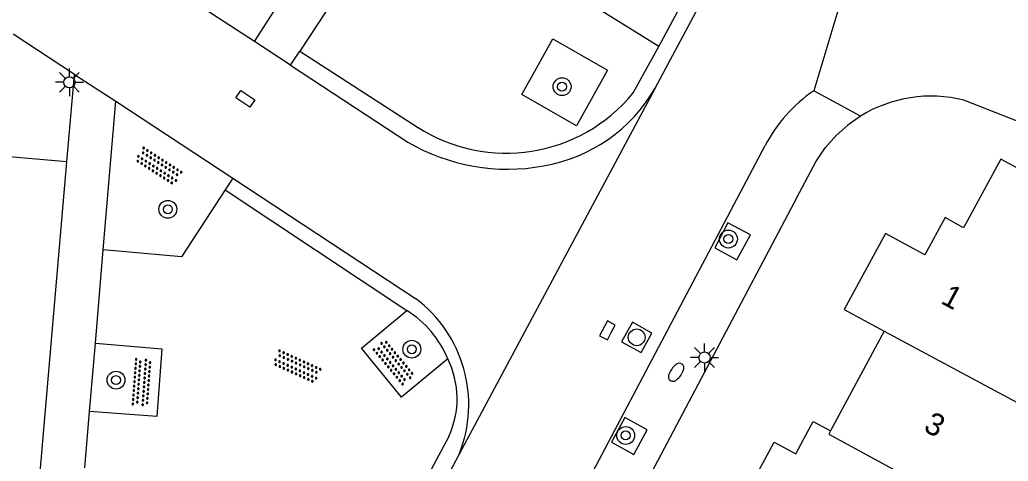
# Model space of a CAD drawing. Extents: x 136000 to 141000, y 400494 to 402006.
# Drawn here: x 137797.28 to 137841.52, y 401678.33 to 401698.08 of the extents above; entities that cross this region are included whole.
import ezdxf

# ---------------------------------------------------------------- set-up
doc = ezdxf.new("R2010")
doc.units = 0
for name, color, linetype in [('gg-afsc-hekwerk', 7, 'Continuous'), ('gg-afsc-muur', 7, 'Continuous'), ('gg-anno-huisnummerreeks BGT', 7, 'Continuous'), ('gg-bbg-hoofdgebouw', 7, 'Continuous'), ('gg-bbg-tussenscheiding', 7, 'Continuous'), ('gg-knt-verharding', 7, 'Continuous'), ('gg-knt-verharding nz', 7, 'Continuous'), ('gt-grn-groengrens', 7, 'Continuous'), ('gt-grn-weggrens', 7, 'Continuous'), ('gt-symb-boom', 7, 'Continuous'), ('gt-symb-brandkraan', 7, 'Continuous'), ('gt-symb-kolk', 7, 'Continuous'), ('gt-symb-kolk center center', 7, 'Continuous'), ('gt-symb-lichtmast', 7, 'Continuous'), ('gt-symb-overige verharding', 7, 'Continuous'), ('gt-symb-rioolschacht', 7, 'Continuous')]:
    doc.layers.add(name, color=color, linetype=linetype)

# ---------------------------------------------------------------- blocks, each defined once
blk = doc.blocks.new('gt0-LMAST')
at = {"layer": 'gt-symb-lichtmast'}
for p, q in [((-0.005, 0.246), (-0.005, 0.621)), ((-0.182, 0.173), (-0.447, 0.438)), ((0.172, 0.173), (0.437, 0.438)), ((-0.255, -0.004), (-0.63, -0.004)), ((-0.182, -0.181), (-0.447, -0.446)), ((-0.005, -0.254), (-0.005, -0.629)), ((0.437, -0.446), (0.172, -0.181)), ((0.245, -0.004), (0.62, -0.004))]:
    blk.add_line(p, q, dxfattribs=at)
blk.add_circle((-0.005, -0.004), 0.25, dxfattribs=at)
blk = doc.blocks.new('gt0-BOOM')
at = {"layer": 'gt-symb-boom'}
for radius in [0.4, 0.2]:
    blk.add_circle((0, 0), radius, dxfattribs=at)
blk = doc.blocks.new('gt0-RS')
at = {"layer": 'gt-symb-rioolschacht'}
blk.add_lwpolyline([(-0.5, -0.5), (0.5, -0.5), (0.5, 0.5), (-0.5, 0.5)], close=True, dxfattribs=at)
blk.add_circle((0, 0), 0.375, dxfattribs=at)
blk = doc.blocks.new('gt0-KOLK')
at = {"layer": 'gt-symb-kolk'}
blk.add_lwpolyline([(0, 0), (0.375, 0), (0.375, 0.4), (-0.375, 0.4), (-0.375, 0), (0, 0)], dxfattribs=at)
blk = doc.blocks.new('gt0-OVH')
at = {"layer": 'gt-symb-overige verharding'}
for points in [[(-0.972, 0.298), (-0.967, 0.308), (-0.965, 0.319), (-0.966, 0.33), (-0.971, 0.34), (-0.978, 0.348), (-0.988, 0.353), (-0.999, 0.355), (-1.01, 0.354), (-1.02, 0.349), (-1.028, 0.342), (-1.033, 0.332), (-1.035, 0.321), (-1.034, 0.31), (-1.029, 0.3), (-1.022, 0.292), (-1.012, 0.287), (-1.001, 0.285), (-0.99, 0.286), (-0.98, 0.291)], [(-0.872, 0.106), (-0.867, 0.116), (-0.865, 0.126), (-0.866, 0.137), (-0.871, 0.147), (-0.878, 0.156), (-0.888, 0.161), (-0.899, 0.163), (-0.91, 0.162), (-0.92, 0.157), (-0.928, 0.15), (-0.933, 0.14), (-0.935, 0.129), (-0.934, 0.118), (-0.929, 0.108), (-0.922, 0.1), (-0.912, 0.095), (-0.901, 0.092), (-0.89, 0.094), (-0.88, 0.098)], [(-0.772, 0.298), (-0.767, 0.308), (-0.765, 0.319), (-0.766, 0.33), (-0.771, 0.34), (-0.778, 0.348), (-0.788, 0.353), (-0.799, 0.355), (-0.81, 0.354), (-0.82, 0.349), (-0.828, 0.342), (-0.833, 0.332), (-0.835, 0.321), (-0.834, 0.31), (-0.829, 0.3), (-0.822, 0.292), (-0.812, 0.287), (-0.801, 0.285), (-0.79, 0.286), (-0.78, 0.291)], [(-0.672, 0.106), (-0.667, 0.116), (-0.665, 0.126), (-0.666, 0.137), (-0.671, 0.147), (-0.678, 0.156), (-0.688, 0.161), (-0.699, 0.163), (-0.71, 0.162), (-0.72, 0.157), (-0.728, 0.15), (-0.733, 0.14), (-0.735, 0.129), (-0.734, 0.118), (-0.729, 0.108), (-0.722, 0.1), (-0.712, 0.095), (-0.701, 0.092), (-0.69, 0.094), (-0.68, 0.098)], [(-0.572, 0.298), (-0.567, 0.308), (-0.565, 0.319), (-0.566, 0.33), (-0.571, 0.34), (-0.578, 0.348), (-0.588, 0.353), (-0.599, 0.355), (-0.61, 0.354), (-0.62, 0.349), (-0.628, 0.342), (-0.633, 0.332), (-0.635, 0.321), (-0.634, 0.31), (-0.629, 0.3), (-0.622, 0.292), (-0.612, 0.287), (-0.601, 0.285), (-0.59, 0.286), (-0.58, 0.291)], [(-0.472, 0.106), (-0.467, 0.116), (-0.465, 0.126), (-0.466, 0.137), (-0.471, 0.147), (-0.478, 0.156), (-0.488, 0.161), (-0.499, 0.163), (-0.51, 0.162), (-0.52, 0.157), (-0.528, 0.15), (-0.533, 0.14), (-0.535, 0.129), (-0.534, 0.118), (-0.529, 0.108), (-0.522, 0.1), (-0.512, 0.095), (-0.501, 0.092), (-0.49, 0.094), (-0.48, 0.098)], [(-0.372, 0.298), (-0.367, 0.308), (-0.365, 0.319), (-0.366, 0.33), (-0.371, 0.34), (-0.378, 0.348), (-0.388, 0.353), (-0.399, 0.355), (-0.41, 0.354), (-0.42, 0.349), (-0.428, 0.342), (-0.433, 0.332), (-0.435, 0.321), (-0.434, 0.31), (-0.429, 0.3), (-0.422, 0.292), (-0.412, 0.287), (-0.401, 0.285), (-0.39, 0.286), (-0.38, 0.291)], [(-0.272, 0.106), (-0.267, 0.116), (-0.265, 0.126), (-0.266, 0.137), (-0.271, 0.147), (-0.278, 0.156), (-0.288, 0.161), (-0.299, 0.163), (-0.31, 0.162), (-0.32, 0.157), (-0.328, 0.15), (-0.333, 0.14), (-0.335, 0.129), (-0.334, 0.118), (-0.329, 0.108), (-0.322, 0.1), (-0.312, 0.095), (-0.301, 0.092), (-0.29, 0.094), (-0.28, 0.098)], [(-0.172, 0.298), (-0.167, 0.308), (-0.165, 0.319), (-0.166, 0.33), (-0.171, 0.34), (-0.178, 0.348), (-0.188, 0.353), (-0.199, 0.355), (-0.21, 0.354), (-0.22, 0.349), (-0.228, 0.342), (-0.233, 0.332), (-0.235, 0.321), (-0.234, 0.31), (-0.229, 0.3), (-0.222, 0.292), (-0.212, 0.287), (-0.201, 0.285), (-0.19, 0.286), (-0.18, 0.291)], [(-0.072, 0.106), (-0.067, 0.116), (-0.065, 0.126), (-0.066, 0.137), (-0.071, 0.147), (-0.078, 0.156), (-0.088, 0.161), (-0.099, 0.163), (-0.11, 0.162), (-0.12, 0.157), (-0.128, 0.15), (-0.133, 0.14), (-0.135, 0.129), (-0.134, 0.118), (-0.129, 0.108), (-0.122, 0.1), (-0.112, 0.095), (-0.101, 0.092), (-0.09, 0.094), (-0.08, 0.098)], [(0.028, 0.298), (0.033, 0.308), (0.035, 0.319), (0.034, 0.33), (0.029, 0.34), (0.022, 0.348), (0.012, 0.353), (0.001, 0.355), (-0.01, 0.354), (-0.02, 0.349), (-0.028, 0.342), (-0.033, 0.332), (-0.035, 0.321), (-0.034, 0.31), (-0.029, 0.3), (-0.022, 0.292), (-0.012, 0.287), (-0.001, 0.285), (0.01, 0.286), (0.02, 0.291)], [(0.128, 0.106), (0.133, 0.116), (0.135, 0.126), (0.134, 0.137), (0.129, 0.147), (0.122, 0.156), (0.112, 0.161), (0.101, 0.163), (0.09, 0.162), (0.08, 0.157), (0.072, 0.15), (0.067, 0.14), (0.065, 0.129), (0.066, 0.118), (0.071, 0.108), (0.078, 0.1), (0.088, 0.095), (0.099, 0.092), (0.11, 0.094), (0.12, 0.098)], [(0.228, 0.298), (0.233, 0.308), (0.235, 0.319), (0.234, 0.33), (0.229, 0.34), (0.222, 0.348), (0.212, 0.353), (0.201, 0.355), (0.19, 0.354), (0.18, 0.349), (0.172, 0.342), (0.167, 0.332), (0.165, 0.321), (0.166, 0.31), (0.171, 0.3), (0.178, 0.292), (0.188, 0.287), (0.199, 0.285), (0.21, 0.286), (0.22, 0.291)], [(0.328, 0.106), (0.333, 0.116), (0.335, 0.126), (0.334, 0.137), (0.329, 0.147), (0.322, 0.156), (0.312, 0.161), (0.301, 0.163), (0.29, 0.162), (0.28, 0.157), (0.272, 0.15), (0.267, 0.14), (0.265, 0.129), (0.266, 0.118), (0.271, 0.108), (0.278, 0.1), (0.288, 0.095), (0.299, 0.092), (0.31, 0.094), (0.32, 0.098)], [(0.428, 0.298), (0.433, 0.308), (0.435, 0.319), (0.434, 0.33), (0.429, 0.34), (0.422, 0.348), (0.412, 0.353), (0.401, 0.355), (0.39, 0.354), (0.38, 0.349), (0.372, 0.342), (0.367, 0.332), (0.365, 0.321), (0.366, 0.31), (0.371, 0.3), (0.378, 0.292), (0.388, 0.287), (0.399, 0.285), (0.41, 0.286), (0.42, 0.291)], [(0.528, 0.106), (0.533, 0.116), (0.535, 0.126), (0.534, 0.137), (0.529, 0.147), (0.522, 0.156), (0.512, 0.161), (0.501, 0.163), (0.49, 0.162), (0.48, 0.157), (0.472, 0.15), (0.467, 0.14), (0.465, 0.129), (0.466, 0.118), (0.471, 0.108), (0.478, 0.1), (0.488, 0.095), (0.499, 0.092), (0.51, 0.094), (0.52, 0.098)], [(0.628, 0.298), (0.633, 0.308), (0.635, 0.319), (0.634, 0.33), (0.629, 0.34), (0.622, 0.348), (0.612, 0.353), (0.601, 0.355), (0.59, 0.354), (0.58, 0.349), (0.572, 0.342), (0.567, 0.332), (0.565, 0.321), (0.566, 0.31), (0.571, 0.3), (0.578, 0.292), (0.588, 0.287), (0.599, 0.285), (0.61, 0.286), (0.62, 0.291)], [(0.728, 0.106), (0.733, 0.116), (0.735, 0.126), (0.734, 0.137), (0.729, 0.147), (0.722, 0.156), (0.712, 0.161), (0.701, 0.163), (0.69, 0.162), (0.68, 0.157), (0.672, 0.15), (0.667, 0.14), (0.665, 0.129), (0.666, 0.118), (0.671, 0.108), (0.678, 0.1), (0.688, 0.095), (0.699, 0.092), (0.71, 0.094), (0.72, 0.098)], [(0.828, 0.298), (0.833, 0.308), (0.835, 0.319), (0.834, 0.33), (0.829, 0.34), (0.822, 0.348), (0.812, 0.353), (0.801, 0.355), (0.79, 0.354), (0.78, 0.349), (0.772, 0.342), (0.767, 0.332), (0.765, 0.321), (0.766, 0.31), (0.771, 0.3), (0.778, 0.292), (0.788, 0.287), (0.799, 0.285), (0.81, 0.286), (0.82, 0.291)], [(0.928, 0.106), (0.933, 0.116), (0.935, 0.126), (0.934, 0.137), (0.929, 0.147), (0.922, 0.156), (0.912, 0.161), (0.901, 0.163), (0.89, 0.162), (0.88, 0.157), (0.872, 0.15), (0.867, 0.14), (0.865, 0.129), (0.866, 0.118), (0.871, 0.108), (0.878, 0.1), (0.888, 0.095), (0.899, 0.092), (0.91, 0.094), (0.92, 0.098)], [(1.028, 0.298), (1.033, 0.308), (1.035, 0.319), (1.034, 0.33), (1.029, 0.34), (1.022, 0.348), (1.012, 0.353), (1.001, 0.355), (0.99, 0.354), (0.98, 0.349), (0.972, 0.342), (0.967, 0.332), (0.965, 0.321), (0.966, 0.31), (0.971, 0.3), (0.978, 0.292), (0.988, 0.287), (0.999, 0.285), (1.01, 0.286), (1.02, 0.291)], [(-0.972, -0.142), (-0.967, -0.132), (-0.965, -0.121), (-0.966, -0.11), (-0.971, -0.1), (-0.978, -0.092), (-0.988, -0.087), (-0.999, -0.085), (-1.01, -0.086), (-1.02, -0.091), (-1.028, -0.098), (-1.033, -0.108), (-1.035, -0.119), (-1.034, -0.13), (-1.029, -0.14), (-1.022, -0.148), (-1.012, -0.153), (-1.001, -0.155), (-0.99, -0.154), (-0.98, -0.149)], [(-0.872, -0.334), (-0.867, -0.324), (-0.865, -0.314), (-0.866, -0.303), (-0.871, -0.293), (-0.878, -0.284), (-0.888, -0.279), (-0.899, -0.277), (-0.91, -0.278), (-0.92, -0.283), (-0.928, -0.29), (-0.933, -0.3), (-0.935, -0.311), (-0.934, -0.322), (-0.929, -0.332), (-0.922, -0.34), (-0.912, -0.345), (-0.901, -0.348), (-0.89, -0.346), (-0.88, -0.342)], [(-0.772, -0.142), (-0.767, -0.132), (-0.765, -0.121), (-0.766, -0.11), (-0.771, -0.1), (-0.778, -0.092), (-0.788, -0.087), (-0.799, -0.085), (-0.81, -0.086), (-0.82, -0.091), (-0.828, -0.098), (-0.833, -0.108), (-0.835, -0.119), (-0.834, -0.13), (-0.829, -0.14), (-0.822, -0.148), (-0.812, -0.153), (-0.801, -0.155), (-0.79, -0.154), (-0.78, -0.149)], [(-0.672, -0.334), (-0.667, -0.324), (-0.665, -0.314), (-0.666, -0.303), (-0.671, -0.293), (-0.678, -0.284), (-0.688, -0.279), (-0.699, -0.277), (-0.71, -0.278), (-0.72, -0.283), (-0.728, -0.29), (-0.733, -0.3), (-0.735, -0.311), (-0.734, -0.322), (-0.729, -0.332), (-0.722, -0.34), (-0.712, -0.345), (-0.701, -0.348), (-0.69, -0.346), (-0.68, -0.342)], [(-0.572, -0.142), (-0.567, -0.132), (-0.565, -0.121), (-0.566, -0.11), (-0.571, -0.1), (-0.578, -0.092), (-0.588, -0.087), (-0.599, -0.085), (-0.61, -0.086), (-0.62, -0.091), (-0.628, -0.098), (-0.633, -0.108), (-0.635, -0.119), (-0.634, -0.13), (-0.629, -0.14), (-0.622, -0.148), (-0.612, -0.153), (-0.601, -0.155), (-0.59, -0.154), (-0.58, -0.149)], [(-0.472, -0.334), (-0.467, -0.324), (-0.465, -0.314), (-0.466, -0.303), (-0.471, -0.293), (-0.478, -0.284), (-0.488, -0.279), (-0.499, -0.277), (-0.51, -0.278), (-0.52, -0.283), (-0.528, -0.29), (-0.533, -0.3), (-0.535, -0.311), (-0.534, -0.322), (-0.529, -0.332), (-0.522, -0.34), (-0.512, -0.345), (-0.501, -0.348), (-0.49, -0.346), (-0.48, -0.342)], [(-0.372, -0.142), (-0.367, -0.132), (-0.365, -0.121), (-0.366, -0.11), (-0.371, -0.1), (-0.378, -0.092), (-0.388, -0.087), (-0.399, -0.085), (-0.41, -0.086), (-0.42, -0.091), (-0.428, -0.098), (-0.433, -0.108), (-0.435, -0.119), (-0.434, -0.13), (-0.429, -0.14), (-0.422, -0.148), (-0.412, -0.153), (-0.401, -0.155), (-0.39, -0.154), (-0.38, -0.149)], [(-0.272, -0.334), (-0.267, -0.324), (-0.265, -0.314), (-0.266, -0.303), (-0.271, -0.293), (-0.278, -0.284), (-0.288, -0.279), (-0.299, -0.277), (-0.31, -0.278), (-0.32, -0.283), (-0.328, -0.29), (-0.333, -0.3), (-0.335, -0.311), (-0.334, -0.322), (-0.329, -0.332), (-0.322, -0.34), (-0.312, -0.345), (-0.301, -0.348), (-0.29, -0.346), (-0.28, -0.342)], [(-0.172, -0.142), (-0.167, -0.132), (-0.165, -0.121), (-0.166, -0.11), (-0.171, -0.1), (-0.178, -0.092), (-0.188, -0.087), (-0.199, -0.085), (-0.21, -0.086), (-0.22, -0.091), (-0.228, -0.098), (-0.233, -0.108), (-0.235, -0.119), (-0.234, -0.13), (-0.229, -0.14), (-0.222, -0.148), (-0.212, -0.153), (-0.201, -0.155), (-0.19, -0.154), (-0.18, -0.149)], [(-0.072, -0.334), (-0.067, -0.324), (-0.065, -0.314), (-0.066, -0.303), (-0.071, -0.293), (-0.078, -0.284), (-0.088, -0.279), (-0.099, -0.277), (-0.11, -0.278), (-0.12, -0.283), (-0.128, -0.29), (-0.133, -0.3), (-0.135, -0.311), (-0.134, -0.322), (-0.129, -0.332), (-0.122, -0.34), (-0.112, -0.345), (-0.101, -0.348), (-0.09, -0.346), (-0.08, -0.342)], [(0.028, -0.142), (0.033, -0.132), (0.035, -0.121), (0.034, -0.11), (0.029, -0.1), (0.022, -0.092), (0.012, -0.087), (0.001, -0.085), (-0.01, -0.086), (-0.02, -0.091), (-0.028, -0.098), (-0.033, -0.108), (-0.035, -0.119), (-0.034, -0.13), (-0.029, -0.14), (-0.022, -0.148), (-0.012, -0.153), (-0.001, -0.155), (0.01, -0.154), (0.02, -0.149)], [(0.128, -0.334), (0.133, -0.324), (0.135, -0.314), (0.134, -0.303), (0.129, -0.293), (0.122, -0.284), (0.112, -0.279), (0.101, -0.277), (0.09, -0.278), (0.08, -0.283), (0.072, -0.29), (0.067, -0.3), (0.065, -0.311), (0.066, -0.322), (0.071, -0.332), (0.078, -0.34), (0.088, -0.345), (0.099, -0.348), (0.11, -0.346), (0.12, -0.342)], [(0.228, -0.142), (0.233, -0.132), (0.235, -0.121), (0.234, -0.11), (0.229, -0.1), (0.222, -0.092), (0.212, -0.087), (0.201, -0.085), (0.19, -0.086), (0.18, -0.091), (0.172, -0.098), (0.167, -0.108), (0.165, -0.119), (0.166, -0.13), (0.171, -0.14), (0.178, -0.148), (0.188, -0.153), (0.199, -0.155), (0.21, -0.154), (0.22, -0.149)], [(0.328, -0.334), (0.333, -0.324), (0.335, -0.314), (0.334, -0.303), (0.329, -0.293), (0.322, -0.284), (0.312, -0.279), (0.301, -0.277), (0.29, -0.278), (0.28, -0.283), (0.272, -0.29), (0.267, -0.3), (0.265, -0.311), (0.266, -0.322), (0.271, -0.332), (0.278, -0.34), (0.288, -0.345), (0.299, -0.348), (0.31, -0.346), (0.32, -0.342)], [(0.428, -0.142), (0.433, -0.132), (0.435, -0.121), (0.434, -0.11), (0.429, -0.1), (0.422, -0.092), (0.412, -0.087), (0.401, -0.085), (0.39, -0.086), (0.38, -0.091), (0.372, -0.098), (0.367, -0.108), (0.365, -0.119), (0.366, -0.13), (0.371, -0.14), (0.378, -0.148), (0.388, -0.153), (0.399, -0.155), (0.41, -0.154), (0.42, -0.149)], [(0.528, -0.334), (0.533, -0.324), (0.535, -0.314), (0.534, -0.303), (0.529, -0.293), (0.522, -0.284), (0.512, -0.279), (0.501, -0.277), (0.49, -0.278), (0.48, -0.283), (0.472, -0.29), (0.467, -0.3), (0.465, -0.311), (0.466, -0.322), (0.471, -0.332), (0.478, -0.34), (0.488, -0.345), (0.499, -0.348), (0.51, -0.346), (0.52, -0.342)], [(0.628, -0.142), (0.633, -0.132), (0.635, -0.121), (0.634, -0.11), (0.629, -0.1), (0.622, -0.092), (0.612, -0.087), (0.601, -0.085), (0.59, -0.086), (0.58, -0.091), (0.572, -0.098), (0.567, -0.108), (0.565, -0.119), (0.566, -0.13), (0.571, -0.14), (0.578, -0.148), (0.588, -0.153), (0.599, -0.155), (0.61, -0.154), (0.62, -0.149)], [(0.728, -0.334), (0.733, -0.324), (0.735, -0.314), (0.734, -0.303), (0.729, -0.293), (0.722, -0.284), (0.712, -0.279), (0.701, -0.277), (0.69, -0.278), (0.68, -0.283), (0.672, -0.29), (0.667, -0.3), (0.665, -0.311), (0.666, -0.322), (0.671, -0.332), (0.678, -0.34), (0.688, -0.345), (0.699, -0.348), (0.71, -0.346), (0.72, -0.342)], [(0.828, -0.142), (0.833, -0.132), (0.835, -0.121), (0.834, -0.11), (0.829, -0.1), (0.822, -0.092), (0.812, -0.087), (0.801, -0.085), (0.79, -0.086), (0.78, -0.091), (0.772, -0.098), (0.767, -0.108), (0.765, -0.119), (0.766, -0.13), (0.771, -0.14), (0.778, -0.148), (0.788, -0.153), (0.799, -0.155), (0.81, -0.154), (0.82, -0.149)], [(0.928, -0.334), (0.933, -0.324), (0.935, -0.314), (0.934, -0.303), (0.929, -0.293), (0.922, -0.284), (0.912, -0.279), (0.901, -0.277), (0.89, -0.278), (0.88, -0.283), (0.872, -0.29), (0.867, -0.3), (0.865, -0.311), (0.866, -0.322), (0.871, -0.332), (0.878, -0.34), (0.888, -0.345), (0.899, -0.348), (0.91, -0.346), (0.92, -0.342)], [(1.028, -0.142), (1.033, -0.132), (1.035, -0.121), (1.034, -0.11), (1.029, -0.1), (1.022, -0.092), (1.012, -0.087), (1.001, -0.085), (0.99, -0.086), (0.98, -0.091), (0.972, -0.098), (0.967, -0.108), (0.965, -0.119), (0.966, -0.13), (0.971, -0.14), (0.978, -0.148), (0.988, -0.153), (0.999, -0.155), (1.01, -0.154), (1.02, -0.149)]]:
    blk.add_lwpolyline(points, close=True, dxfattribs=at)
blk = doc.blocks.new('gt0-KOLKCC')
at = {"layer": 'gt-symb-kolk center center'}
blk.add_lwpolyline([(-0.375, 0.2), (0.375, 0.2), (0.375, -0.2), (-0.375, -0.2)], close=True, dxfattribs=at)
blk = doc.blocks.new('gt0-BR')
at = {"layer": 'gt-symb-brandkraan'}
for centre, radius, start, end in [((-0.244, 0), 0.206, 107.5669, 252.4331), ((0.599, -2.664), 3, 106.892, 107.5669), ((0, -0.691), 0.938, 73.108, 106.892), ((-0.599, -2.664), 3, 72.4331, 73.108), ((0.244, 0), 0.206, 287.567, 72.4331), ((0.599, 2.664), 3, 252.4331, 253.108), ((0, 0.691), 0.938, 253.108, 286.8921), ((-0.599, 2.664), 3, 286.8921, 287.567)]:
    blk.add_arc(centre, radius, start, end, dxfattribs=at)

msp = doc.modelspace()

# ---------------------------------------------------------------- linework, layer by layer
at = {"layer": 'gg-afsc-hekwerk'}
msp.add_line((137799.384, 401691.73), (137795.819, 401692.04), dxfattribs=at)
at = {"layer": 'gg-afsc-muur'}
msp.add_line((137859.293, 401686.702), (137839.536, 401694.481), dxfattribs=at)
msp.add_lwpolyline([(137832.057, 401690.136), (137832.9, 401691.73), (137833.322, 401692.35), (137833.817, 401692.912), (137834.333, 401693.371)], dxfattribs=at)
msp.add_arc((137838.054, 401688.678), 5.989, 75.6735, 121.7687, dxfattribs=at)
at = {"layer": 'gg-bbg-hoofdgebouw'}
msp.add_line((137835.959, 401684.148), (137833.562, 401679.686), dxfattribs=at)
for points in [[(137846.028, 401681.809), (137844.278, 401682.763), (137847.34, 401688.518), (137841.179, 401691.841), (137839.52, 401688.78)], [(137839.52, 401688.78), (137838.69, 401689.23), (137837.791, 401687.557)], [(137837.791, 401687.557), (137836.018, 401688.518), (137834.173, 401685.116), (137835.959, 401684.148)], [(137829.186, 401675.756), (137831.036, 401679.183), (137832.003, 401678.664), (137832.71, 401679.964)], [(137832.71, 401679.964), (137832.786, 401680.105), (137833.562, 401679.686)]]:
    msp.add_lwpolyline(points, dxfattribs=at)
at = {"layer": 'gg-bbg-tussenscheiding'}
msp.add_line((137835.959, 401684.148), (137844.758, 401679.427), dxfattribs=at)
msp.add_lwpolyline([(137833.562, 401679.686), (137833.485, 401679.542), (137840.594, 401675.671)], dxfattribs=at)
at = {"layer": 'gg-knt-verharding'}
for p, q in [((137807.788, 401697.112), (137809.752, 401700.178)), ((137811.492, 401699.232), (137809.804, 401696.677)), ((137799.72, 401695.63), (137796.977, 401697.434)), ((137809.396, 401696.06), (137807.788, 401697.112)), ((137809.396, 401696.06), (137809.804, 401696.677)), ((137809.804, 401696.677), (137815.071, 401693.277)), ((137824.726, 401694.81), (137825.88, 401696.886)), ((137809.396, 401696.06), (137814.649, 401692.611)), ((137799.384, 401691.73), (137799.72, 401695.63)), ((137799.72, 401695.63), (137801.58, 401694.44)), ((137801.015, 401687.784), (137801.58, 401694.44)), ((137801.58, 401694.44), (137806.808, 401690.998)), ((137834.901, 401693.77), (137834.333, 401693.371)), ((137796.771, 401661.23), (137799.384, 401691.73)), ((137806.808, 401690.998), (137806.469, 401690.477)), ((137806.808, 401690.998), (137814.99, 401685.61)), ((137806.469, 401690.477), (137814.603, 401685.074)), ((137832.057, 401690.136), (137813.166, 401654.412)), ((137800.66, 401683.604), (137801.015, 401687.784)), ((137800.401, 401680.552), (137800.66, 401683.604)), ((137800.186, 401678.027), (137800.401, 401680.552)), ((137816.475, 401679.44), (137813.007, 401672.94))]:
    msp.add_line(p, q, dxfattribs=at)
for points in [[(137825.718, 401695.029), (137829.467, 401702.072), (137829.83, 401703.066), (137833.785, 401718.726)], [(137807.788, 401697.112), (137804.26, 401699.409), (137805.508, 401701.253)], [(137825.88, 401696.886), (137823.09, 401698.626), (137823.157, 401698.735)], [(137822.19, 401693.337), (137819.745, 401694.735), (137821.135, 401697.226), (137823.581, 401695.824), (137822.19, 401693.337)], [(137806.469, 401690.477), (137804.511, 401687.469), (137801.015, 401687.784)], [(137828.971, 401689.001), (137828.378, 401687.871), (137829.375, 401687.334), (137829.982, 401688.457), (137828.971, 401689.001)], [(137816.429, 401682.912), (137814.367, 401681.2), (137812.572, 401683.386), (137814.603, 401685.074)], [(137800.66, 401683.604), (137803.638, 401683.359), (137803.414, 401680.329), (137800.401, 401680.552)], [(137824.351, 401680.279), (137823.757, 401679.176), (137824.761, 401678.627), (137825.353, 401679.733), (137824.351, 401680.279)], [(137816.941, 401678.642), (137805.251, 401656.45), (137804.999, 401655.931)]]:
    msp.add_lwpolyline(points, dxfattribs=at)
for centre, radius, start, end in [((137819.04, 401699.451), 7.34, 237.2651, 320.7789), ((137819.524, 401698.589), 7.144, 279.596, 330.1094), ((137819.109, 401700.198), 8.801, 239.5515, 280.5144), ((137811.439, 401680.859), 5.932, 338.0577, 53.2262), ((137812.182, 401681.177), 4.587, 22.2184, 58.1497), ((137812.865, 401681.128), 3.985, 334.934, 26.5841)]:
    msp.add_arc(centre, radius, start, end, dxfattribs=at)
at = {"layer": 'gg-knt-verharding nz'}
for p, q in [((137834.901, 401693.77), (137832.81, 401694.911)), ((137811.121, 401655.529), (137830.641, 401692.463))]:
    msp.add_line(p, q, dxfattribs=at)
msp.add_arc((137836.762, 401689.224), 6.925, 124.7986, 152.1176, dxfattribs=at)
at = {"layer": 'gt-grn-groengrens'}
msp.add_lwpolyline([(137825.88, 401696.886), (137828.813, 401702.364), (137829.147, 401703.277), (137831.503, 401712.577)], dxfattribs=at)
at = {"layer": 'gt-grn-weggrens'}
for p, q in [((137837.02, 401708.918), (137832.81, 401694.911)), ((137825.718, 401695.029), (137816.941, 401678.642))]:
    msp.add_line(p, q, dxfattribs=at)

# ---------------------------------------------------------------- block references
at = {"layer": 'gt-symb-boom'}
for p in [(137821.548, 401695.09), (137803.903, 401689.603), (137828.993, 401688.27), (137814.822, 401683.339), (137801.585, 401681.957), (137824.395, 401679.481)]:
    msp.add_blockref('gt0-BOOM', p, dxfattribs=at)
at = {"layer": 'gt-symb-brandkraan', "rotation": -125.39110751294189}
msp.add_blockref('gt0-BR', (137826.655, 401682.309), dxfattribs=at)
at = {"layer": 'gt-symb-kolk', "rotation": 61.97468394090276}
msp.add_blockref('gt0-KOLK', (137823.751, 401684.087), dxfattribs=at)
at = {"layer": 'gt-symb-kolk center center', "rotation": -33.24493724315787}
msp.add_blockref('gt0-KOLKCC', (137807.374, 401694.546), dxfattribs=at)
at = {"layer": 'gt-symb-lichtmast'}
for p in [(137799.503, 401695.289), (137827.929, 401682.973)]:
    msp.add_blockref('gt0-LMAST', p, dxfattribs=at)
at = {"layer": 'gt-symb-overige verharding'}
for p, rotation in [((137803.488, 401691.533), -32.67327747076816), ((137814.016, 401682.755), 129.76890883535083), ((137809.68, 401682.563), -24.38706671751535), ((137802.729, 401681.863), 85.75513794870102)]:
    msp.add_blockref('gt0-OVH', p, dxfattribs=dict(at, rotation=rotation))
at = {"layer": 'gt-symb-rioolschacht', "rotation": -29.154810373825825}
msp.add_blockref('gt0-RS', (137824.888, 401683.871), dxfattribs=at)

# ---------------------------------------------------------------- texts
at = {"layer": 'gg-anno-huisnummerreeks BGT'}
for s, rotation, p in [('1', 331.5, (137838.449, 401685.423)), ('3', 331.8, (137837.676, 401679.712))]:
    msp.add_text(s, height=1, rotation=rotation, dxfattribs=at).set_placement(p)

doc.saveas('drawing.dxf')
